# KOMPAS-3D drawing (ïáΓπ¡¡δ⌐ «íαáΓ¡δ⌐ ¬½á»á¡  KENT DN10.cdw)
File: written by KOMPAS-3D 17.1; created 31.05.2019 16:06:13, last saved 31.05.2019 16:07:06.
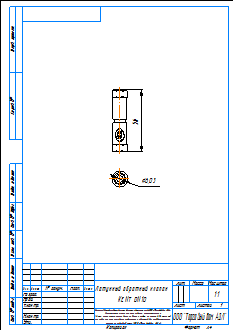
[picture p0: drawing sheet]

Sheet 1: A4, portrait

Title block, sheet 1: name: Латунный обратный клапан / KENT DN10; material: Внимание! Данный продукт является объектом авторского права ООО «Торговый Дом АДЛ». / Запрещается изменение, копирование, распространение / (в том числе путем копирования на другие сайты и ресурсы в Интернете) / или любое иное использование информации и объектов без предварительного / согласия правообладателя (ООО «Торговый Дом АДЛ»).; sheets: 1; organisation: ООО "Торговый дом АДЛ"; sheet format: A4

Views: Вид 1, Проекционный вид 2
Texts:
  user
Dimensions and other numbers on the sheet: 6,03; 56; 1:1; 1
